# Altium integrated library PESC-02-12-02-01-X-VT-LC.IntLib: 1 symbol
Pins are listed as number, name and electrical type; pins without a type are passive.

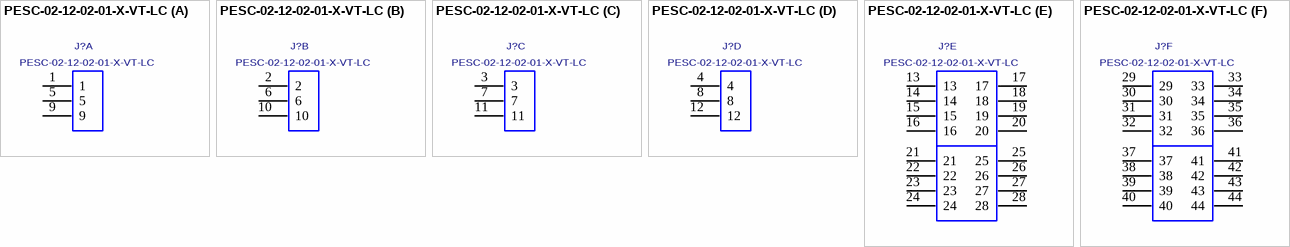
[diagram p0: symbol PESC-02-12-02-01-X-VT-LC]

## PESC-02-12-02-01-X-VT-LC
designator J?
VERTICAL POWER SOCKET. 2 POWER PINS PER END, 12 SINGAL PINS.; MANUFACTURER: SAMTEC
footprint PESC-02-12-02-01-X-VT-LC
part A pins: 1, 5, 9
part B pins: 2, 6, 10
part C pins: 3, 7, 11
part D pins: 4, 8, 12
part E pins: 13, 14, 15, 16, 17, 18, 19, 20, 21, 22, 23, 24, 25, 26, 27, 28
part F pins: 29, 30, 31, 32, 33, 34, 35, 36, 37, 38, 39, 40, 41, 42, 43, 44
